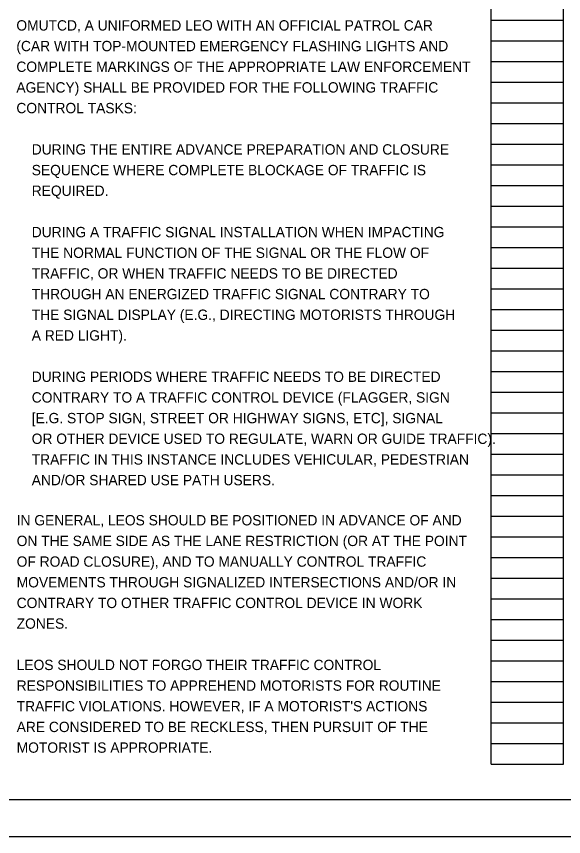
# Model space of a CAD drawing. Extents: x 0 to 34, y 0 to 22.
# Drawn here: x 17.24 to 24.66, y 0 to 11.11 of the extents above; entities that cross this region are included whole.
import ezdxf

# ---------------------------------------------------------------- set-up
doc = ezdxf.new("R2010")
doc.units = 0
for name, color, linetype in [('SH_Border', 7, 'Continuous'), ('SH_Cut_Line', 7, 'Continuous'), ('SH_Data', 7, 'Continuous'), ('SH_Text', 7, 'Continuous')]:
    doc.layers.add(name, color=color, linetype=linetype)

msp = doc.modelspace()

# ---------------------------------------------------------------- linework, layer by layer
at = {"layer": 'SH_Border'}
msp.add_lwpolyline([(1.5, 21.5), (33.5, 21.5), (33.5, 0.5), (1.5, 0.5)], close=True, dxfattribs=at)
at = {"layer": 'SH_Cut_Line'}
msp.add_lwpolyline([(0, 0), (34, 0), (34, 22), (0, 22)], close=True, dxfattribs=at)
at = {"layer": 'SH_Data'}
for p, q in [((23.68, 0.98), (23.68, 21.14)), ((24.66, 0.98), (24.66, 21.14)), ((23.68, 11.06), (24.66, 11.06)), ((23.68, 10.78), (24.66, 10.78)), ((23.68, 10.5), (24.66, 10.5)), ((23.68, 10.22), (24.66, 10.22)), ((23.68, 9.94), (24.66, 9.94)), ((23.68, 9.66), (24.66, 9.66)), ((23.68, 9.38), (24.66, 9.38)), ((23.68, 9.1), (24.66, 9.1)), ((23.68, 8.82), (24.66, 8.82)), ((23.68, 8.54), (24.66, 8.54)), ((23.68, 8.26), (24.66, 8.26)), ((23.68, 7.98), (24.66, 7.98)), ((23.68, 7.7), (24.66, 7.7)), ((23.68, 7.42), (24.66, 7.42)), ((23.68, 7.14), (24.66, 7.14)), ((23.68, 6.86), (24.66, 6.86)), ((23.68, 6.58), (24.66, 6.58)), ((23.68, 6.3), (24.66, 6.3)), ((23.68, 6.02), (24.66, 6.02)), ((23.68, 5.74), (24.66, 5.74)), ((23.68, 5.46), (24.66, 5.46)), ((23.68, 5.18), (24.66, 5.18)), ((23.68, 4.9), (24.66, 4.9)), ((23.68, 4.62), (24.66, 4.62)), ((23.68, 4.34), (24.66, 4.34)), ((23.68, 4.06), (24.66, 4.06)), ((23.68, 3.78), (24.66, 3.78)), ((23.68, 3.5), (24.66, 3.5)), ((23.68, 3.22), (24.66, 3.22)), ((23.68, 2.94), (24.66, 2.94)), ((23.68, 2.66), (24.66, 2.66)), ((23.68, 2.38), (24.66, 2.38)), ((23.68, 2.1), (24.66, 2.1)), ((23.68, 1.82), (24.66, 1.82)), ((23.68, 1.54), (24.66, 1.54)), ((23.68, 1.26), (24.66, 1.26)), ((23.68, 0.98), (24.66, 0.98))]:
    msp.add_line(p, q, dxfattribs=at)

# ---------------------------------------------------------------- texts
at = {"layer": 'SH_Text'}
for s, p in [('OMUTCD, A UNIFORMED LEO WITH AN OFFICIAL PATROL CAR', (17.24, 10.92)), ('(CAR WITH TOP-MOUNTED EMERGENCY FLASHING LIGHTS AND', (17.24, 10.64)), ('COMPLETE MARKINGS OF THE APPROPRIATE LAW ENFORCEMENT', (17.24, 10.36)), ('AGENCY) SHALL BE PROVIDED FOR THE FOLLOWING TRAFFIC', (17.24, 10.08)), ('CONTROL TASKS:', (17.24, 9.8)), ('    DURING THE ENTIRE ADVANCE PREPARATION AND CLOSURE', (17.24, 9.24)), ('    SEQUENCE WHERE COMPLETE BLOCKAGE OF TRAFFIC IS', (17.24, 8.96)), ('    REQUIRED.', (17.24, 8.68)), ('    DURING A TRAFFIC SIGNAL INSTALLATION WHEN IMPACTING', (17.24, 8.12)), ('    THE NORMAL FUNCTION OF THE SIGNAL OR THE FLOW OF', (17.24, 7.84)), ('    TRAFFIC, OR WHEN TRAFFIC NEEDS TO BE DIRECTED', (17.24, 7.56)), ('    THROUGH AN ENERGIZED TRAFFIC SIGNAL CONTRARY TO', (17.24, 7.28)), ('    THE SIGNAL DISPLAY (E.G., DIRECTING MOTORISTS THROUGH', (17.24, 7)), ('    A RED LIGHT).', (17.24, 6.72)), ('    DURING PERIODS WHERE TRAFFIC NEEDS TO BE DIRECTED', (17.24, 6.16)), ('    CONTRARY TO A TRAFFIC CONTROL DEVICE (FLAGGER, SIGN', (17.24, 5.88)), ('    [E.G. STOP SIGN, STREET OR HIGHWAY SIGNS, ETC], SIGNAL', (17.24, 5.6)), ('    OR OTHER DEVICE USED TO REGULATE, WARN OR GUIDE TRAFFIC).', (17.24, 5.32)), ('    TRAFFIC IN THIS INSTANCE INCLUDES VEHICULAR, PEDESTRIAN', (17.24, 5.04)), ('    AND/OR SHARED USE PATH USERS.', (17.24, 4.76)), ('IN GENERAL, LEOS SHOULD BE POSITIONED IN ADVANCE OF AND', (17.244, 4.216)), ('ON THE SAME SIDE AS THE LANE RESTRICTION (OR AT THE POINT', (17.244, 3.936)), ('OF ROAD CLOSURE), AND TO MANUALLY CONTROL TRAFFIC', (17.244, 3.656)), ('MOVEMENTS THROUGH SIGNALIZED INTERSECTIONS AND/OR IN', (17.244, 3.376)), ('CONTRARY TO OTHER TRAFFIC CONTROL DEVICE IN WORK', (17.244, 3.096)), ('ZONES.', (17.244, 2.816)), ('LEOS SHOULD NOT FORGO THEIR TRAFFIC CONTROL', (17.244, 2.256)), ('RESPONSIBILITIES TO APPREHEND MOTORISTS FOR ROUTINE', (17.244, 1.976)), ("TRAFFIC VIOLATIONS. HOWEVER, IF A MOTORIST'S ACTIONS", (17.244, 1.696)), ('ARE CONSIDERED TO BE RECKLESS, THEN PURSUIT OF THE', (17.244, 1.416)), ('MOTORIST IS APPROPRIATE.', (17.244, 1.136))]:
    msp.add_text(s, height=0.14, dxfattribs=at).set_placement(p)

doc.saveas('drawing.dxf')
